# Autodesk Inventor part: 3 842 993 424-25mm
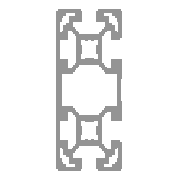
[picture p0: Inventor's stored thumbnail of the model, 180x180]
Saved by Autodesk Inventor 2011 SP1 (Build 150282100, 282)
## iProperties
Category: End -/-
Created: 2011-02
Part Number: 3 842 993 424-25mm
Document SubType Name: Modeling
Designer: SRW
Density: 2.71 g/cm^3
Categories: <MemberInstance><Categories><Category DisplayName="Structural Shapes" InternalName="089c4875-fa83-4c05-b084-43b9cc11f5ed" Mnemonic="GRDR"><CategoryParameter Dis
Stock Number: 3 842 993 424
Description: PROFILE 40x80 4S, -/-
Material: Aluminum-6061
Mass: 68.7122 g
Surface Area: 237.468 cm^2
Volume: 25.3551 cm^3
G_L: 25.000 mm
Author: SRW
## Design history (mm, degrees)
node "Blocks"
  sketch "40X80"
    geometry: L1 (26.765, 27.076)-(27.682, 26.676); L2 (37.765, 22.28)-(36.849, 22.68); L3 (27.682, 22.68)-(26.765, 22.28); L4 (26.765, 19.178)-(29.868, 19.178); L5 (26.765, 22.28)-(26.765, 19.178); L6 (29.868, 19.178)-(30.267, 20.095); L7 (34.264, 20.095)-(34.663, 19.178); L8 (34.663, 19.178)-(37.765, 19.178); L9 (37.765, 19.178)-(37.765, 22.28); L10 (36.849, 26.676)-(37.765, 27.076); L11 (43.73, 14.628)-(39.765, 18.592); L12 (46.265, 14.628)-(43.73, 14.628); L13 (46.265, 19.678)-(46.265, 14.628); L14 (50.765, 19.678)-(46.265, 19.678); L15 (50.765, 18.878)-(50.765, 19.678); L16 (52.265, 18.878)-(50.765, 18.878); L17 (52.265, 7.787)-(52.265, 18.878); L18 (38.065, 4.787)-(49.265, 4.787); L19 (38.065, 6.287)-(38.065, 4.787); L20 (37.265, 6.287)-(38.065, 6.287); L21 (37.265, 10.787)-(37.265, 6.287); L22 (42.315, 10.787)-(37.265, 10.787); L23 (42.315, 13.322)-(42.315, 10.787); L24 (38.351, 17.287)-(42.315, 13.322); L25 (47.765, 15.178)-(47.765, 12.928); L26 (47.765, 12.928)-(46.765, 12.928); L27 (44.015, 9.178)-(41.765, 9.178); L28 (44.015, 10.178)-(44.015, 9.178); L29 (41.765, 6.178)-(46.765, 6.178); L30 (46.765, 6.178)-(46.765, 7.428); L31 (49.515, 10.178)-(50.765, 10.178); L32 (50.765, 10.178)-(50.765, 15.178); L33 (13.765, 29.678)-(13.765, 19.678); L34 (18.265, 19.678)-(13.765, 19.678); L35 (18.265, 14.628)-(18.265, 19.678); L36 (20.801, 14.628)-(18.265, 14.628); L37 (24.765, 18.592)-(20.801, 14.628); L38 (22.215, 13.322)-(26.18, 17.287); L39 (22.215, 10.787)-(22.215, 13.322); L40 (27.265, 10.787)-(22.215, 10.787); L41 (27.265, 6.287)-(27.265, 10.787); L42 (26.465, 6.287)-(27.265, 6.287); L43 (26.465, 4.787)-(26.465, 6.287); L44 (15.265, 4.787)-(26.465, 4.787); L45 (20.515, 9.178)-(20.515, 10.178); L46 (22.765, 9.178)-(20.515, 9.178); L47 (16.765, 12.928)-(16.765, 15.178); L48 (17.765, 12.928)-(16.765, 12.928); L49 (13.765, 15.178)-(13.765, 10.178); L50 (13.765, 10.178)-(15.015, 10.178); L51 (17.765, 6.178)-(22.765, 6.178); L52 (17.765, 7.428)-(17.765, 6.178); L53 (46.765, 82.145)-(46.765, 83.395); L54 (20.801, 74.945)-(24.765, 70.981); L55 (18.265, 74.945)-(20.801, 74.945); L56 (18.265, 69.895)-(18.265, 74.945); L57 (13.765, 69.895)-(18.265, 69.895); L58 (12.265, 81.787)-(12.265, 7.787); L59 (26.465, 84.787)-(15.265, 84.787); L60 (26.465, 83.287)-(26.465, 84.787); L61 (27.265, 83.287)-(26.465, 83.287); L62 (27.265, 78.787)-(27.265, 83.287); L63 (22.215, 78.787)-(27.265, 78.787); L64 (22.215, 76.251)-(22.215, 78.787)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; A1 r 5 centre (32.265, 24.678) between (36.849, 22.68) and (36.849, 26.676); A2 r 5 centre (32.265, 24.678) between (27.682, 26.676) and (27.682, 22.68); A3 r 5 centre (32.265, 24.678) between (30.267, 20.095) and (34.264, 20.095); A4 r 3 centre (49.265, 7.787) between (49.265, 4.787) and (52.265, 7.787); A5 r 1.5 centre (49.265, 15.178) between (50.765, 15.178) and (47.765, 15.178); A6 r 1.5 centre (41.765, 7.678) between (41.765, 9.178) and (41.765, 6.178); A7 r 2.75 centre (46.765, 10.178) between (46.765, 12.928) and (44.015, 10.178); A8 r 2.75 centre (46.765, 10.178) between (46.765, 7.428) and (49.515, 10.178); A9 r 3 centre (15.265, 7.787) between (12.265, 7.787) and (15.265, 4.787); A10 r 1.5 centre (15.265, 15.178) between (16.765, 15.178) and (13.765, 15.178); A11 r 2.75 centre (17.765, 10.178) between (20.515, 10.178) and (17.765, 12.928); A12 r 2.75 centre (17.765, 10.178) between (15.015, 10.178) and (17.765, 7.428); A13 r 1.5 centre (22.765, 7.678) between (22.765, 6.178) and (22.765, 9.178); A14 r 3 centre (15.265, 81.787) between (15.265, 84.787) and (12.265, 81.787); A15 r 1.5 centre (22.765, 81.895) between (22.765, 80.395) and (22.765, 83.395); A16 r 2.75 centre (17.765, 79.395) between (17.765, 76.645) and (20.515, 79.395); A17 r 1.5 centre (15.265, 74.395) between (13.765, 74.395) and (16.765, 74.395); A18 r 2.75 centre (17.765, 79.395) between (17.765, 82.145) and (15.015, 79.395); A19 r 1.5 centre (41.765, 81.895) between (41.765, 83.395) and (41.765, 80.395); A20 r 2.75 centre (46.765, 79.395) between (49.515, 79.395) and (46.765, 82.145); A21 r 2.75 centre (46.765, 79.395) between (44.015, 79.395) and (46.765, 76.645); A22 r 1.5 centre (49.265, 74.395) between (47.765, 74.395) and (50.765, 74.395); A23 r 3 centre (49.265, 81.787) between (52.265, 81.787) and (49.265, 84.787); A24 r 5 centre (32.265, 64.895) between (34.264, 69.478) and (30.267, 69.478); A25 r 5 centre (32.265, 64.895) between (36.849, 62.897) and (36.849, 66.893); A26 r 5 centre (32.265, 64.895) between (30.267, 60.312) and (34.264, 60.312); A27 r 5 centre (32.265, 64.895) between (27.682, 66.893) and (27.682, 62.897); A28 r 5 centre (32.265, 24.678) between (34.264, 29.261) and (30.267, 29.261); 1 further point
    constraints: 320 end point, 56 point on circle, 28 centre point, 1 coincident
node "Start Plane"
node "End Plane"
sketch "Sketch1"
  geometry: 1 further point
  constraints: 1 other
extrude "Body" new body sketch "Sketch1" stored distance "d4" = 0.13; taper "d5" = 0 deg
node "Driven Length"
  sketch "Sketch51"
    geometry: L1 (0, 0)-(10, 0) reference
    constraints: 2 end point, 1 horizontal
  workplane "Work Plane22"
  sketch "Sketch52"
    geometry: L1 (-28, 0)-(28, 0) reference; L2 (-28, 25)-(28, 25) reference
    dimensions: "d7" = 25 distance between parallel lines of L1 L2 (derived)
sketch "Sketch9"
  geometry: 2 further points
  constraints: 1 vertical alignment
  dimensions: "d88" = 40 distance of point (0, 0) point (0, -40)
hole "M12/-" sketch "Sketch9" at (0, 0), (0, -40) diameter "d17" = 10.106; stored, may be unused: countersink angle "d21" = 90 deg, drill point angle "d23" = 118 deg; dims "d18" = 6, "d19" = 4, "d20" = 2, "d22" = 55
sketch "Sketch10"
  geometry: 2 further points
  constraints: 1 vertical alignment
  dimensions: "d89" = 40 distance of point (0, 0) point (0, -40)
hole "-/M12" sketch "Sketch10" at (0, 0), (0, -40) diameter "d24" = 10.106; stored, may be unused: countersink angle "d28" = 90 deg, drill point angle "d30" = 118 deg; dims "d25" = 6, "d26" = 4, "d27" = 2, "d29" = 55
sketch "Sketch11"
  geometry: L1 (-13.7, 0)-(12.2, 0) reference; C1 r 8.5 at (0, 20); 1 further point
  constraints: 1 centre point, 1 vertical alignment
  dimensions: "d31" = 20 distance from line of C1.centre L1; "d32" = 17 diameter of C1
extrude "D17VS/-" cut sketch "Sketch11" stored distance "d33" = 10; taper "d34" = 0 deg
sketch "Sketch12"
  geometry: L1 (-13.7, 25)-(12.2, 25) reference; C1 r 8.5 at (0, 5); 1 further point
  constraints: 1 centre point, 1 vertical alignment
  dimensions: "d35" = 17 diameter of C1; "d36" = 20 distance from line of L1 C1.centre
extrude "-/D17VS" cut sketch "Sketch12" stored distance "d37" = 10; taper "d38" = 0 deg
sketch "Sketch13"
  geometry: L1 (-12.98, 0)-(7.88, 0) reference; C1 r 4.9 at (0, 20); 1 further point
  constraints: 1 centre point, 1 vertical alignment
  dimensions: "d39" = 9.8 diameter of C1; "d40" = 20 distance from line of C1.centre L1
extrude "D9.8VS/-" cut sketch "Sketch13" stored distance "d41" = 10; taper "d42" = 0 deg
sketch "Sketch14"
  geometry: L1 (-12.98, 25)-(7.88, 25) reference; C1 r 4.9 at (0, 5); 1 further point
  constraints: 1 centre point, 1 vertical alignment
  dimensions: "d43" = 9.8 diameter of C1; "d44" = 20 distance from line of L1 C1.centre
extrude "-/D9.8VS" cut sketch "Sketch14" stored distance "d45" = 10; taper "d46" = 0 deg
sketch "Sketch15"
  geometry: L1 (-54.86, 25)-(14.86, 25) reference; C1 r 4.9 at (0, 5); C2 r 4.9 at (-40, 5); 1 further point
  constraints: 2 centre point, 1 equal radius, 1 horizontal alignment, 1 vertical alignment
  dimensions: "d47" = 9.8 diameter of C1; "d48" = 20 distance from line of L1 C1.centre; "d92" = 40 distance of C1.centre C2.centre
extrude "-/D9.8" cut sketch "Sketch15" stored distance "d49" = 10; taper "d50" = 0 deg
sketch "Sketch26"
  geometry: L1 (-54.86, 0)-(14.86, 0) reference; C1 r 4.9 at (0, 20); C2 r 4.9 at (-40, 20); 1 further point
  constraints: 2 centre point, 1 equal radius, 1 horizontal alignment, 1 vertical alignment
  dimensions: "d62" = 9.8 diameter of C1; "d65" = 20 distance from line of L1 C1.centre; "d93" = 40 distance of C1.centre C2.centre
extrude "D9.8/-" cut sketch "Sketch26" stored distance "d63" = 10; taper "d64" = 0 deg
sketch "Sketch37"
  geometry: L1 (-59.9, 0)-(19.9, 0) reference; L2 (-59.9, 25)-(19.9, 25) reference; C1 r 8.5 at (0, 20); C2 r 8.5 at (-40, 20); 1 further point
  constraints: 2 centre point, 1 equal radius, 1 horizontal alignment, 1 vertical alignment
  dimensions: "d76" = 20 distance from line of C1.centre L1; "d77" = 17 diameter of C1; "d90" = 40 distance of C1.centre C2.centre
extrude "D17/-" cut sketch "Sketch37" stored distance "d78" = 10; taper "d79" = 0 deg
sketch "Sketch38"
  geometry: L1 (-59.9, 25)-(19.9, 25) reference; C1 r 8.5 at (0, 5); C2 r 8.5 at (-40, 5); 1 further point
  constraints: 2 centre point, 1 equal radius, 1 horizontal alignment, 1 vertical alignment
  dimensions: "d80" = 17 diameter of C1; "d81" = 20 distance from line of L1 C1.centre; "d91" = 40 distance of C1.centre C2.centre
extrude "-/D17" cut sketch "Sketch38" stored distance "d82" = 10; taper "d83" = 0 deg
body "Solid1"
node "40X80:1"
other parameters: "Length" = 25, "G_OFFSET_START" = 0 [user parameter; used in 2 equation terms], "G_OFFSET_END" = 0 [user parameter; used in 2 equation terms], "d2" = 0 (computed from G_OFFSET_START), "d3" = 25 (= Length + G_OFFSET_END), "G_L" = 25 (= d7) [user parameter], "d102" = 90 deg, "Length2" = 25 (= G_OFFSET_START + Length + G_OFFSET_END) [user parameter]
